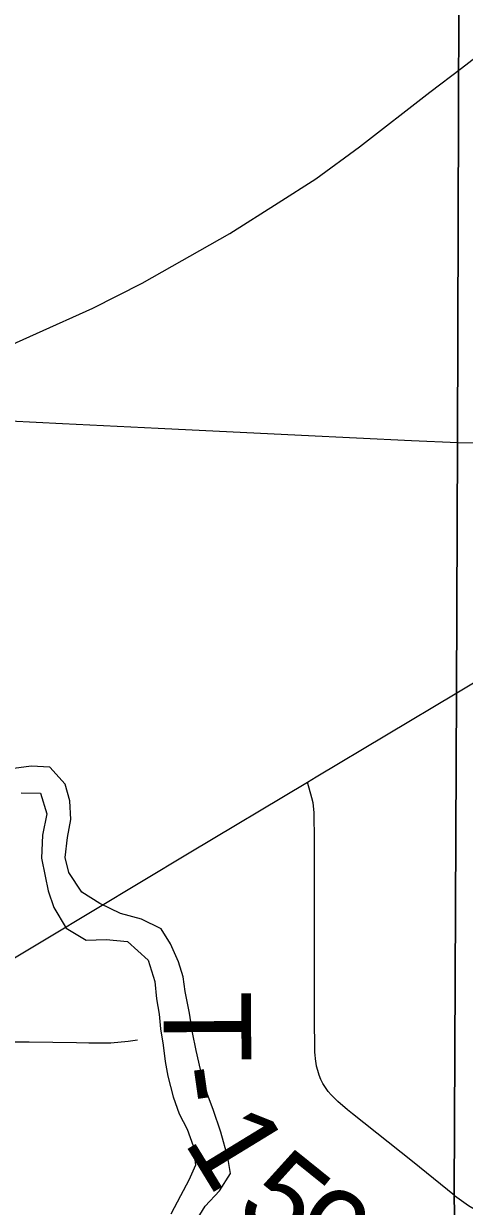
# Model space of a CAD drawing. Extents: x 0 to 45.9, y 0 to 22.
# Drawn here: x 5.194 to 5.48, y 18.714 to 19.483 of the extents above; entities that cross this region are included whole.
import ezdxf

# ---------------------------------------------------------------- set-up
doc = ezdxf.new("R2010")
doc.units = 0
for name, color, linetype in [('Default', 7, 'Continuous'), ('GM_X_County_Road', 7, 'Continuous'), ('GM_X_Major_River', 7, 'Continuous'), ('GM_X_Rail_Line', 7, 'Continuous'), ('GM_X_State_Route', 7, 'Continuous'), ('GM_X_Township_Road', 7, 'Continuous'), ('GM_X_Township_Road_Text', 7, 'Continuous'), ('SH_Text', 7, 'Continuous')]:
    doc.layers.add(name, color=color, linetype=linetype)

msp = doc.modelspace()

# ---------------------------------------------------------------- linework, layer by layer
at = {"layer": 'Default'}
msp.add_lwpolyline([(2.1, 19.71136), (2.1, 14.1), (5.4538, 14.1), (5.46055, 15.65881), (5.46505, 16.7018), (5.46936, 17.70607), (5.48021, 18.3214), (5.47374, 18.72155), (5.47524, 19.0482), (5.47587, 19.21088), (5.47734, 19.71076), (5.08255, 19.71199), (3.73665, 19.70719), (2.14996, 19.71128)], close=True, dxfattribs=at)
msp.add_lwpolyline([(5.47734, 19.71076), (5.47587, 19.21088), (5.47524, 19.0482), (5.47374, 18.72155), (5.48021, 18.3214), (5.46936, 17.70607), (5.46505, 16.7018), (5.46055, 15.65881), (5.4538, 14.1)], dxfattribs=at)
at = {"layer": 'GM_X_County_Road'}
msp.add_lwpolyline([(5.47396, 18.72101), (5.48309, 18.71458), (5.48776, 18.71167), (5.49256, 18.70953), (5.49914, 18.7082), (5.51135, 18.70761), (5.58904, 18.71003), (5.66047, 18.71226), (5.75869, 18.71555)], dxfattribs=at)
at = {"layer": 'GM_X_Major_River'}
for points in [[(5.30885, 18.80298), (5.30608, 18.81519), (5.30367, 18.82701), (5.30167, 18.83959), (5.29894, 18.8537), (5.29762, 18.86322), (5.29442, 18.87278), (5.28937, 18.88466), (5.28313, 18.89428), (5.27039, 18.90063), (5.25684, 18.90433), (5.24334, 18.91069), (5.23176, 18.91814), (5.22332, 18.93085), (5.22088, 18.94078), (5.22229, 18.95366), (5.22443, 18.96539), (5.22393, 18.97756), (5.22075, 18.98826), (5.21076, 18.99948), (5.19866, 19.00011), (5.18423, 18.99813)], [(5.19224, 18.98278), (5.20472, 18.98251), (5.20899, 18.96913), (5.20604, 18.95514), (5.20535, 18.94034), (5.20775, 18.92852), (5.20982, 18.91898), (5.21338, 18.90827), (5.22143, 18.89481), (5.23451, 18.88694), (5.2474, 18.88743), (5.26138, 18.886), (5.27475, 18.87395), (5.27901, 18.86019), (5.28028, 18.84877), (5.28196, 18.83886), (5.2829, 18.82934), (5.28457, 18.81867), (5.28586, 18.80801), (5.28755, 18.79848), (5.29105, 18.78512), (5.29498, 18.77402), (5.30007, 18.76404), (5.30401, 18.75333), (5.30564, 18.74076), (5.30127, 18.73097), (5.29576, 18.72084), (5.28944, 18.70882)], [(5.30484, 18.7028), (5.31189, 18.71404), (5.32119, 18.7241), (5.32824, 18.73535), (5.32657, 18.74564), (5.32199, 18.76207), (5.31701, 18.77698), (5.31342, 18.78655), (5.30885, 18.80298)]]:
    msp.add_lwpolyline(points, dxfattribs=at)
at = {"layer": 'GM_X_Rail_Line'}
msp.add_line((5.4785, 19.45379), (5.81835, 19.71689), dxfattribs=at)
msp.add_lwpolyline([(2.1, 18.01462), (2.16534, 18.0407), (2.52368, 18.18391), (2.7751, 18.28526), (3.11448, 18.42274), (3.32536, 18.50906), (3.73896, 18.67777), (4.02896, 18.79612), (4.52201, 18.99753), (5.11085, 19.24258), (5.16496, 19.26464), (5.20223, 19.28132), (5.23885, 19.29783), (5.27089, 19.31401), (5.32778, 19.34638), (5.35933, 19.36616), (5.38369, 19.38186), (5.41213, 19.40262), (5.45791, 19.43809), (5.4785, 19.45379)], dxfattribs=at)
at = {"layer": 'GM_X_State_Route'}
for points in [[(5.47546, 19.04766), (5.56513, 19.10157)], [(4.97878, 18.77439), (4.98991, 18.77828), (5.02204, 18.78981), (5.03939, 18.7966), (5.05937, 18.80516), (5.08192, 18.81557), (5.09855, 18.82398), (5.12038, 18.83582), (5.1261, 18.83916), (5.16057, 18.85927), (5.20848, 18.88791), (5.30153, 18.94379), (5.37843, 18.98975), (5.38405, 18.9931), (5.47546, 19.04766)]]:
    msp.add_lwpolyline(points, dxfattribs=at)
at = {"layer": 'GM_X_Township_Road'}
for points in [[(5.18477, 19.22443), (5.219, 19.22287), (5.28118, 19.2198), (5.37449, 19.21527), (5.44601, 19.21178), (5.4761, 19.21033)], [(5.4761, 19.21033), (5.53063, 19.21013), (5.77415, 19.21469), (5.78047, 19.2142), (5.78365, 19.21341), (5.78663, 19.21197), (5.78923, 19.20989), (5.7913, 19.2073), (5.79281, 19.2044), (5.79734, 19.19574)], [(5.38392, 18.8071), (5.38375, 18.80811), (5.3832, 18.81423), (5.38291, 18.83786), (5.38283, 18.85153), (5.38291, 18.87334), (5.38291, 18.90449), (5.38297, 18.9512), (5.3827, 18.96995), (5.38206, 18.97625), (5.38121, 18.97939), (5.37843, 18.98975)], [(5.14438, 18.82439), (5.14533, 18.82381), (5.14821, 18.82282), (5.15121, 18.82221), (5.15428, 18.82181), (5.16348, 18.82116), (5.17272, 18.82084), (5.19734, 18.82083), (5.22809, 18.82047), (5.23622, 18.82017), (5.25053, 18.82033), (5.26171, 18.82132), (5.26795, 18.82215)], [(5.40443, 18.77669), (5.39811, 18.78203), (5.39378, 18.78636), (5.39181, 18.7887), (5.39001, 18.79114), (5.38841, 18.79372), (5.38704, 18.79642), (5.38588, 18.79921), (5.38497, 18.80214), (5.38426, 18.80509), (5.38392, 18.8071)], [(5.47396, 18.72101), (5.44657, 18.74301), (5.40758, 18.77402), (5.40443, 18.77669)]]:
    msp.add_lwpolyline(points, dxfattribs=at)
at = {"layer": 'SH_Text'}
for points in [[(5.4538, 14.1), (5.46055, 15.65881), (5.46505, 16.7018), (5.46936, 17.70607), (5.48021, 18.3214), (5.47374, 18.72155), (5.47524, 19.0482), (5.47587, 19.21088), (5.47734, 19.71076)], [(5.47734, 19.71076), (5.47587, 19.21088), (5.47524, 19.0482), (5.47374, 18.72155), (5.48021, 18.3214), (5.46936, 17.70607), (5.46505, 16.7018), (5.46055, 15.65881), (5.4538, 14.1)]]:
    msp.add_lwpolyline(points, dxfattribs=at)

# ---------------------------------------------------------------- texts
at = {"layer": 'GM_X_Township_Road_Text'}
for s, rotation, p in [('T', 270.32572, (5.28475, 18.85379)), ('-', 278.13334, (5.28562, 18.80287)), ('1', 301.42848, (5.29738, 18.75624)), ('5', 321.15884, (5.32964, 18.71042)), ('9', 322.08629, (5.35769, 18.68785))]:
    msp.add_text(s, height=0.05682, rotation=rotation, dxfattribs=at).set_placement(p)

doc.saveas('drawing.dxf')
